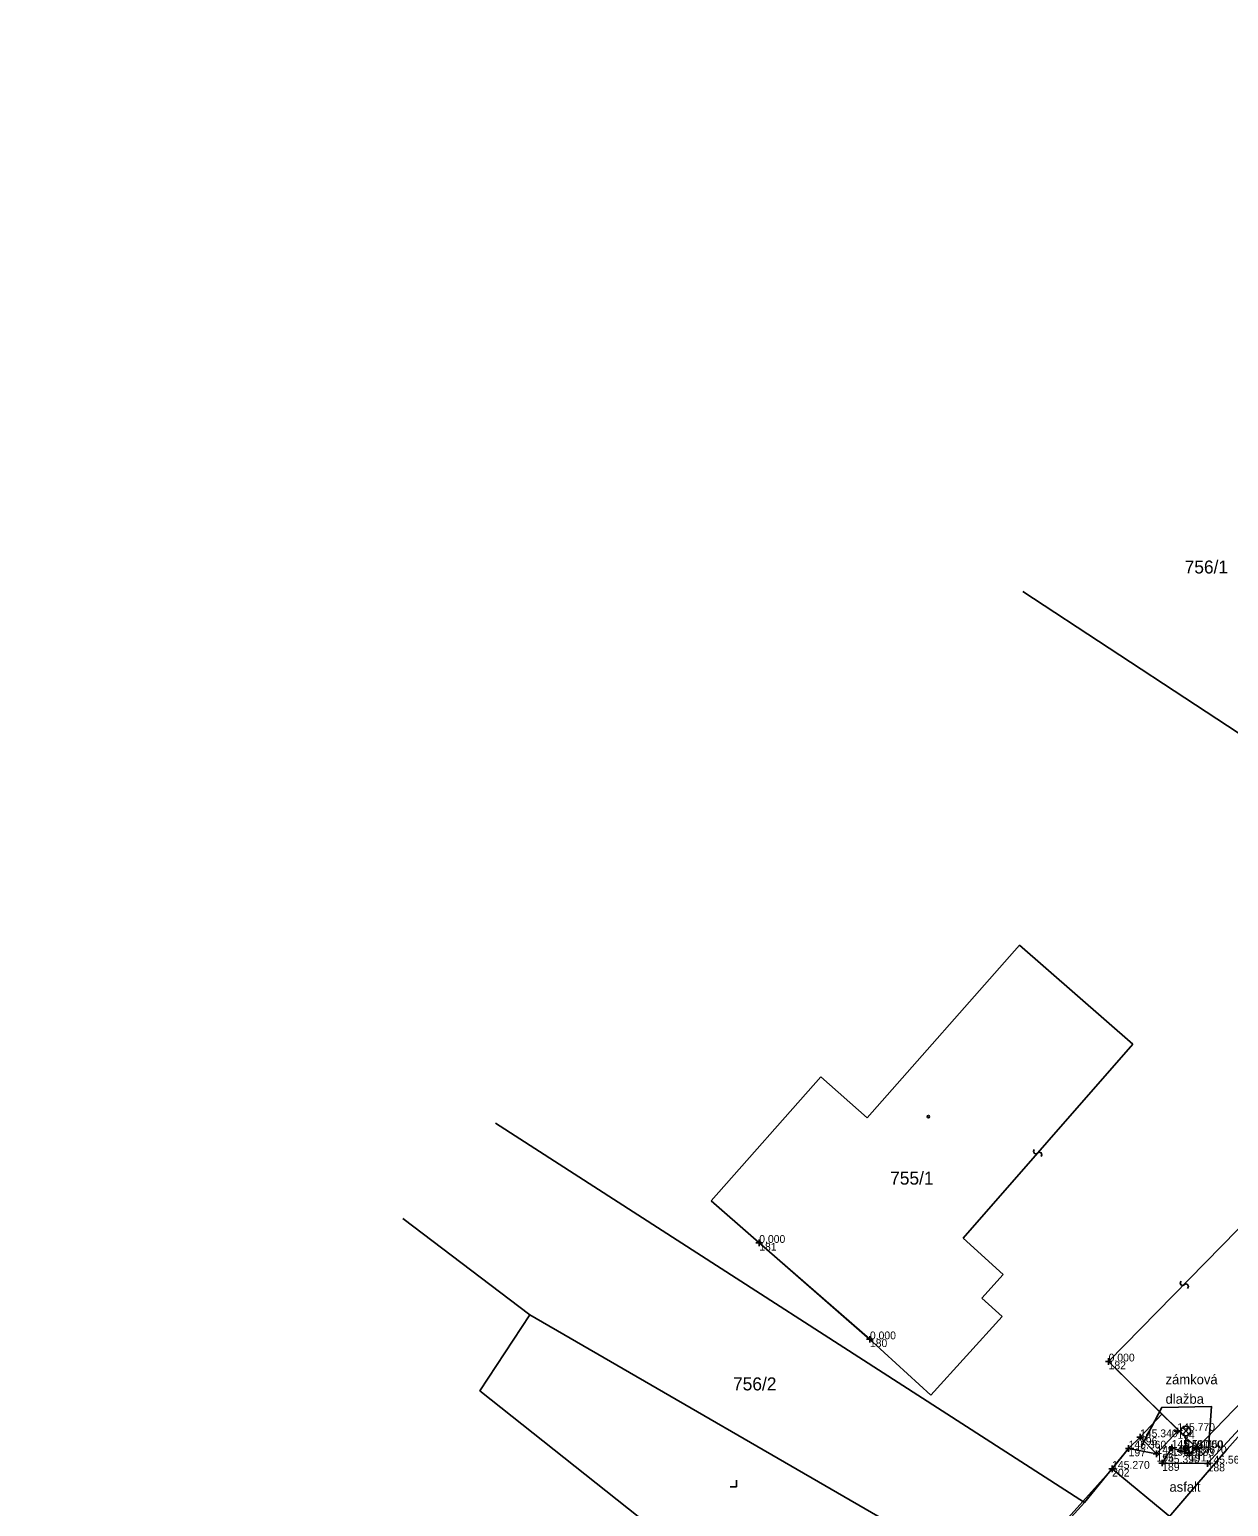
# Model space of a CAD drawing. Extents: x -748509 to -748117, y -967868 to -967533.
# Drawn here: x -748408.1 to -748315.7, y -967668.1 to -967554.3 of the extents above; entities that cross this region are included whole.
import ezdxf

# ---------------------------------------------------------------- set-up
doc = ezdxf.new("R2010")
doc.units = 0
for name, color, linetype in [('Body polohopisu', 7, 'Continuous'), ('Budovy', 7, 'Continuous'), ('Doplňkové značky', 7, 'Continuous'), ('Doplňující texty', 7, 'Continuous'), ('KM', 7, 'Continuous'), ('Ploty_opěrné zdi', 7, 'Continuous'), ('Popisy objektů_povrchů', 7, 'Continuous'), ('Rozhraní ploch', 7, 'Continuous'), ('Vnitřní kresba', 7, 'Continuous'), ('Vstup na pozemek', 7, 'Continuous'), ('Výšky bodů', 7, 'Continuous'), ('Čísla bodů', 7, 'Continuous')]:
    doc.layers.add(name, color=color, linetype=linetype)

msp = doc.modelspace()

# ---------------------------------------------------------------- linework, layer by layer
at = {"layer": 'Body polohopisu'}
for p, q in [((-748351.87, -967647.83), (-748352.12, -967647.83)), ((-748351.87, -967647.83), (-748351.87, -967647.58)), ((-748351.87, -967647.83), (-748351.62, -967647.83)), ((-748351.87, -967647.83), (-748351.87, -967648.08)), ((-748343.34, -967655.26), (-748343.34, -967655.01)), ((-748343.34, -967655.26), (-748343.59, -967655.26)), ((-748343.34, -967655.26), (-748343.09, -967655.26)), ((-748343.34, -967655.26), (-748343.34, -967655.51)), ((-748324.94, -967656.97), (-748325.19, -967656.97)), ((-748324.94, -967656.97), (-748324.94, -967656.72)), ((-748324.94, -967656.97), (-748324.69, -967656.97)), ((-748324.94, -967656.97), (-748324.94, -967657.22)), ((-748322.52, -967662.81), (-748322.77, -967662.81)), ((-748322.52, -967662.81), (-748322.52, -967662.56)), ((-748322.52, -967662.81), (-748322.27, -967662.81)), ((-748322.52, -967662.81), (-748322.52, -967663.06)), ((-748319.64, -967662.33), (-748319.89, -967662.33)), ((-748319.64, -967662.33), (-748319.64, -967662.08)), ((-748319.64, -967662.33), (-748319.39, -967662.33)), ((-748319.64, -967662.33), (-748319.64, -967662.58)), ((-748323.4, -967663.68), (-748323.65, -967663.68)), ((-748323.4, -967663.68), (-748323.4, -967663.43)), ((-748323.4, -967663.68), (-748323.15, -967663.68)), ((-748323.4, -967663.68), (-748323.4, -967663.93)), ((-748321.25, -967664.09), (-748321.5, -967664.09)), ((-748321.25, -967664.09), (-748321.25, -967663.84)), ((-748321.25, -967664.09), (-748321, -967664.09)), ((-748321.25, -967664.09), (-748321.25, -967664.34)), ((-748320.08, -967663.63), (-748320.33, -967663.63)), ((-748320.08, -967663.63), (-748320.08, -967663.38)), ((-748320.08, -967663.63), (-748319.83, -967663.63)), ((-748320.08, -967663.63), (-748320.08, -967663.88)), ((-748318.99, -967663.65), (-748319.24, -967663.65)), ((-748318.99, -967663.65), (-748318.99, -967663.4)), ((-748318.99, -967663.65), (-748318.74, -967663.65)), ((-748318.99, -967663.65), (-748318.99, -967663.9)), ((-748318.74, -967664.07), (-748318.99, -967664.07)), ((-748318.74, -967664.07), (-748318.74, -967663.82)), ((-748318.74, -967664.07), (-748318.49, -967664.07)), ((-748318.74, -967664.07), (-748318.74, -967664.32)), ((-748318.15, -967663.66), (-748318.4, -967663.66)), ((-748318.15, -967663.66), (-748318.15, -967663.41)), ((-748318.15, -967663.66), (-748317.9, -967663.66)), ((-748318.15, -967663.66), (-748318.15, -967663.91)), ((-748324.67, -967665.24), (-748324.92, -967665.24)), ((-748324.67, -967665.24), (-748324.67, -967664.99)), ((-748324.67, -967665.24), (-748324.42, -967665.24)), ((-748324.67, -967665.24), (-748324.67, -967665.49)), ((-748320.81, -967664.8), (-748321.06, -967664.8)), ((-748320.81, -967664.8), (-748320.81, -967664.55)), ((-748320.81, -967664.8), (-748320.56, -967664.8)), ((-748320.81, -967664.8), (-748320.81, -967665.05)), ((-748317.31, -967664.84), (-748317.56, -967664.84)), ((-748317.31, -967664.84), (-748317.31, -967664.59)), ((-748317.31, -967664.84), (-748317.06, -967664.84)), ((-748317.31, -967664.84), (-748317.31, -967665.09))]:
    msp.add_line(p, q, dxfattribs=at)
at = {"layer": 'Budovy'}
for points in [[(-748343.34, -967655.26), (-748351.87, -967647.83)], [(-748310.91, -967648.32), (-748308.28, -967650.99), (-748307.98, -967651.29), (-748309.61, -967654.82), (-748318.15, -967663.66), (-748324.94, -967656.97)]]:
    msp.add_lwpolyline(points, dxfattribs=at)
at = {"layer": 'Doplňkové značky'}
for p, q in [((-748319.25, -967662.59), (-748318.73, -967662.06)), ((-748318.72, -967662.58), (-748319.25, -967662.06)), ((-748318.99, -967662.7), (-748318.99, -967663.45))]:
    msp.add_line(p, q, dxfattribs=at)
for centre, radius in [((-748318.99, -967662.33), 0.375), ((-748318.99, -967663.65), 0.2)]:
    msp.add_circle(centre, radius, dxfattribs=at)
at = {"layer": 'Doplňující texty'}
msp.add_lwpolyline([(-748322.43, -967663.54), (-748320.84, -967660.51), (-748317.01, -967660.43), (-748317.27, -967663.99)], dxfattribs=at)
at = {"layer": 'KM'}
for p, q in [((-748372.19, -967638.6), (-748326.81, -967667.85)), ((-748369.55, -967653.37), (-748379.33, -967645.96)), ((-748337.03, -967672.18), (-748369.55, -967653.37)), ((-748353.62, -967666.62), (-748353.62, -967666.12)), ((-748354.12, -967666.62), (-748353.62, -967666.62))]:
    msp.add_line(p, q, dxfattribs=at)
for points in [[(-748245.23, -967554.32), (-748248, -967560.09), (-748251.25, -967566.35), (-748259.98, -967584.86), (-748268.35, -967600.05), (-748271.49, -967604.68), (-748279.6, -967616.66), (-748283.52, -967622.09), (-748309.26, -967655.94), (-748313.11, -967660.69), (-748315.81, -967663.73), (-748339.38, -967691.21), (-748366.68, -967719.8), (-748398.22, -967751.73), (-748421.72, -967775.27), (-748446.6, -967799.82), (-748468.93, -967821.53), (-748491.86, -967845.1), (-748500.53, -967854.44)], [(-748303.96, -967602.45), (-748311.58, -967610.73), (-748331.56, -967597.63)], [(-748326.81, -967667.85), (-748323.4, -967663.68), (-748322.52, -967662.81), (-748320.84, -967661.02), (-748318.15, -967663.66), (-748309.61, -967654.82), (-748307.98, -967651.29), (-748308.35, -967650.91), (-748310.6, -967648.68), (-748293.45, -967627.35), (-748285.77, -967619.07)], [(-748341.64, -967684.43), (-748373.4, -967659.23), (-748369.55, -967653.37)], [(-748333.33, -967675.02), (-748329.42, -967670.54), (-748327.83, -967668.97), (-748326.81, -967667.85)]]:
    msp.add_lwpolyline(points, dxfattribs=at)
msp.add_circle((-748338.83, -967638.1), 0.0875, dxfattribs=at)
at = {"layer": 'Ploty_opěrné zdi'}
msp.add_lwpolyline([(-748323.4, -967663.68), (-748322.52, -967662.81), (-748321.25, -967664.09), (-748319.64, -967662.33)], dxfattribs=at)
at = {"layer": 'Rozhraní ploch'}
for points in [[(-748318.15, -967663.66), (-748318.74, -967664.07), (-748320.08, -967663.63), (-748320.81, -967664.8), (-748317.31, -967664.84), (-748311.17, -967658.18), (-748308.97, -967655.34), (-748295.87, -967638.09), (-748283.23, -967621.44), (-748271.46, -967604.65), (-748272.46, -967602.39)], [(-748321.25, -967664.09), (-748323.4, -967663.68)], [(-748324.67, -967665.24), (-748320.08, -967669.05), (-748329.48, -967679.42), (-748339.41, -967690.9), (-748340.94, -967689.97)]]:
    msp.add_lwpolyline(points, dxfattribs=at)
at = {"layer": 'Vnitřní kresba'}
for p, q in [((-748331.8, -967624.88), (-748343.54, -967638.19)), ((-748323.07, -967632.51), (-748331.8, -967624.88)), ((-748336.15, -967647.46), (-748323.07, -967632.51)), ((-748347.12, -967635.03), (-748355.57, -967644.59)), ((-748343.54, -967638.19), (-748347.12, -967635.03)), ((-748355.57, -967644.59), (-748343.15, -967655.46)), ((-748313.74, -967645.55), (-748324.94, -967656.97)), ((-748333.06, -967650.27), (-748336.15, -967647.46)), ((-748334.7, -967652.08), (-748333.06, -967650.27)), ((-748333.14, -967653.5), (-748334.7, -967652.08)), ((-748338.64, -967659.56), (-748333.14, -967653.5)), ((-748343.15, -967655.46), (-748338.64, -967659.56)), ((-748324.94, -967656.97), (-748320.84, -967661.02))]:
    msp.add_line(p, q, dxfattribs=at)
for points in [[(-748330.68, -967640.64), (-748330.74, -967640.79), (-748330.66, -967640.93), (-748330.52, -967640.97), (-748330.3, -967640.84), (-748330.15, -967640.89), (-748330.09, -967641.04), (-748330.15, -967641.17)], [(-748318.85, -967651.34), (-748318.78, -967651.2), (-748318.85, -967651.04), (-748319, -967651), (-748319.23, -967651.11), (-748319.37, -967651.06), (-748319.42, -967650.91), (-748319.36, -967650.78)]]:
    msp.add_lwpolyline(points, dxfattribs=at)
at = {"layer": 'Vstup na pozemek'}
msp.add_lwpolyline([(-748323.4, -967663.68), (-748324.67, -967665.24), (-748329.42, -967670.54)], dxfattribs=at)

# ---------------------------------------------------------------- texts
at = {"layer": 'KM'}
for s, p in [('756/1', (-748319.08, -967596.24)), ('755/1', (-748341.78, -967643.34)), ('756/2', (-748353.89, -967659.2))]:
    msp.add_text(s, height=1, dxfattribs=at).set_placement(p)
at = {"layer": 'Popisy objektů_povrchů'}
for s, p in [('zámková', (-748320.55, -967658.73)), ('dlažba', (-748320.55, -967660.23)), ('asfalt', (-748320.25, -967667.01))]:
    msp.add_text(s, height=0.75, dxfattribs=at).set_placement(p)
at = {"layer": 'Výšky bodů'}
for s, p in [('0.000', (-748351.87, -967647.83)), ('0.000', (-748343.34, -967655.26)), ('0.000', (-748324.94, -967656.97)), ('145.770', (-748319.64, -967662.33)), ('145.360', (-748323.4, -967663.68)), ('145.340', (-748322.52, -967662.81)), ('145.510', (-748320.08, -967663.63)), ('145.750', (-748318.99, -967663.65)), ('0.000', (-748318.15, -967663.66)), ('145.410', (-748321.25, -967664.09)), ('145.390', (-748320.81, -967664.8)), ('145.670', (-748318.74, -967664.07)), ('145.560', (-748317.31, -967664.84)), ('145.270', (-748324.67, -967665.24))]:
    msp.add_text(s, height=0.6, dxfattribs=at).set_placement(p)
at = {"layer": 'Čísla bodů'}
for s, p in [('181', (-748351.87, -967648.43)), ('180', (-748343.34, -967655.86)), ('182', (-748324.94, -967657.57)), ('196', (-748322.52, -967663.41)), ('194', (-748319.64, -967662.93)), ('197', (-748323.4, -967664.28)), ('195', (-748321.25, -967664.69)), ('190', (-748320.08, -967664.23)), ('193', (-748318.99, -967664.25)), ('191', (-748318.74, -967664.67)), ('183', (-748318.15, -967664.26)), ('202', (-748324.67, -967665.84)), ('189', (-748320.81, -967665.4)), ('188', (-748317.31, -967665.44))]:
    msp.add_text(s, height=0.6, dxfattribs=at).set_placement(p)

doc.saveas('drawing.dxf')
